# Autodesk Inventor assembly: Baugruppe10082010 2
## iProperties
Created: 2010-08
Part Number: Baugruppe10082010 2
Document SubType Name: Assembly
Designer: Administrator
_SolveAssemblyDoc: Frame Generator Solve Assembly
_Version: 13.0.0
Author: Administrator
